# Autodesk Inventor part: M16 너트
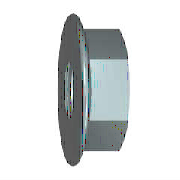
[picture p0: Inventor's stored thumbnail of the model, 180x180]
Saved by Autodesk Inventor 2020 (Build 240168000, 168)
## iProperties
Created: 2009-02
Part Number: M16 너트
Material: 강철, 연강
Document SubType Name: Modeling
Standard: JIS B 1190
Designer: mdu
Standards Organization: JIS
Language: ko-KR
Size Designation: M 16
Categories: <MemberInstance><Categories><Category DisplayName="조임쇠" InternalName="e4da775c-781d-43d5-af7c-5136215cf5a6" Mnemonic="FSTN"><Category DisplayName="너트" InternalN
Density: 1 g/cm^3
Appearance: 니켈
IsCustomPart: 0
Author: mdu
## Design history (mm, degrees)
sketch "스케치1"
  geometry: L1 (-3.414, 0)-(18.069, 0) reference; L2 (6.015, 11)-(3.359, 15.6); L3 (6.015, 11)-(15, 11); L4 (15, 11)-(15, 0); L5 (6.015, 11)-(6.015, 0); L6 (0, -3.378)-(0, 20.266) reference; A1 r 1.8 centre (1.8, 14.7) between (3.359, 15.6) and (0, 14.7); 1 further point
  constraints: 8 end point, 3 point on line, 2 perpendicular, 2 point on circle, 2 tangent, 1 centre point, 1 parallel
  dimensions: "d2" = 22 diameter of L3 L1 (= SW); "d4" = 33 dimension on A1 L1 (= LADI); "d5" = 1.8 radius of A1 (= PHH); "d15" = 15 distance between parallel lines of L4 L6 (= KOH); "d16" = 30 deg angle of L6 L2 (= KEWI)
revolve "링" sketch "스케치1" stored, may be unused: angle "d8" = 90 deg
sketch "스케치2"
  geometry: L1 (-11, -6.351)-(-11, 6.351); L2 (-11, 6.351)-(0, 12.702); L3 (0, 12.702)-(11, 6.351); L4 (11, 6.351)-(11, -6.351); L5 (11, -6.351)-(0, -12.702); L6 (0, -12.702)-(-11, -6.351); C1 r 4.9 at (0, 0); C2 r 14.7 at (0, 0) reference; 1 further point
  constraints: 12 end point, 1 centre point, 1 coincident, 1 vertical, 11 other
  dimensions: "d6" = 25.40341 distance of L5.end L2.end (= 1.1547 x SW)
extrude "본체" join sketch "스케치2" distance "d7" = 15 (= KOH); taper "d9" = 0 deg
sketch "스케치3"
  geometry: L1 (5.032, 12.702)-(15, 12.702) reference; L2 (15, 6.351)-(15, 12.702) reference; L3 (0, -14.7)-(0, 14.7) reference; L4 (-3, 0)-(18, 0) reference; L5 (14.018, 12.702)-(15, 11)
  constraints: 2 end point, 2 point on line
  dimensions: "d10" = 30 deg angle of L2 L5 (= ANG1); "d11" = 22 diameter of L5.end L4 (= SW0)
revolve "모따기1" sketch "스케치3" stored, may be unused: angle "d24" = 90 deg
sketch "스케치4"
  geometry: C1 r 14.7 at (0, 0) reference; 1 further point
  constraints: 1 coincident
hole "스레드" sketch "스케치4" at (0, 0) diameter "d25" = 13.835; stored, may be unused: countersink angle "d29" = 82 deg, drill point angle "d31" = 118 deg; dims "d26" = 6, "d27" = 4, "d28" = 2, "d30" = 8
workaxis "Work Axis1"
workplane "Work Plane1"
body "Solid1"
chamfer "모따기2" distance "d12" = 1.08253 (= -0.5 x GD1 + 0.5 x NND); stored, may be unused: angle "d13" = 30 deg, second distance "d46" = 1.08253 (= -0.5 x GD1 + 0.5 x NND)
chamfer "모따기3" distance "d51" = 1.08253 (= -0.5 x GD1 + 0.5 x NND); stored, may be unused: second distance "d52" = 2, angle "d53" = 45 deg
other parameters: "ANG1" = 30 deg [user parameter; used in 1 equation term], "KEWI" = 30 deg [user parameter; used in 1 equation term], "NND" = 16 [user parameter; used in 3 equation terms], "LADI" = 33 [user parameter; used in 2 equation terms], "SW" = 22 [user parameter; used in 4 equation terms], "PHH" = 1.8 [user parameter; used in 2 equation terms], "KOH" = 15 [user parameter; used in 2 equation terms], "SW0" = 22 (= SW) [user parameter; used in 1 equation term], "GD1" = 13.83494 (computed from THREADDIA, PTC, TOA) [user parameter; used in 3 equation terms], "d1" = 33 (= LADI), "d3" = 1.8 (= PHH), "d45" = 0, "d47" = 0, "d49" = 0, "d54" = 0, "GUL" = 1.08253 (= 0.541266 x PTC) [user parameter], "TPU" = 5 (computed from PTC) [user parameter], "RR" = 2 [user parameter], "THREADDIA" = 16 [user parameter; used in 1 equation term], "TOA" = 30 deg [user parameter; used in 1 equation term], "PTC" = 2 [user parameter; used in 4 equation terms], "GAL" = 1.08253 (= 0.541266 x PTC) [user parameter], "E0" = 25.41 (= 1.155 x SW) [user parameter]
